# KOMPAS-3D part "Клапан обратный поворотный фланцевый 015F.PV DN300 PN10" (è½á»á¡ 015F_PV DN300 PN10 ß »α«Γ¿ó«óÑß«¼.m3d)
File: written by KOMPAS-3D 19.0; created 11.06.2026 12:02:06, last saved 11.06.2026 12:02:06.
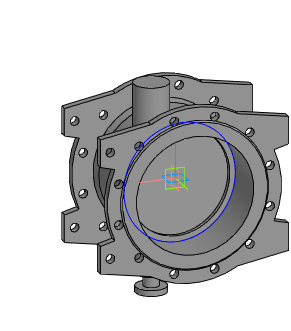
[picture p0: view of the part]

Document properties: Автор: Энергия; Полное имя файла: Z:\3.Личные\kachalov\001_3d для проектировщиков\5.5 Тип 015F.PV Клапан обратный поворотный с двумя эксцентриками\_stp_Клапан 015F.PV DN300-DN1200 с противовесом\Клапан 015F_PV DN300 PN10 с противовесом.m3d

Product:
- Part/product: Клапан обратный поворотный фланцевый 015F.PV DN300 PN10

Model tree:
1. Операция без истории:1
2. Сплайн:1
     Координата Y = 30; Координата Z = 150; Вес = 1; Координата X = 300; Координата Y = 69.4957; Координата Z = 150; Вес = 0.333333; Координата X = 300; Координата Y = 69.4957; Координата Z = -150; Вес = 0.333333; Координата Y = 30; Координата Z = -150; Вес = 1; Координата X = -300; Координата Y = -9.49575; Координата Z = -150; Вес = 0.333333; Координата X = -300; Координата Y = -9.49575; Координата Z = 150; Вес = 0.333333; Порядок = 4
